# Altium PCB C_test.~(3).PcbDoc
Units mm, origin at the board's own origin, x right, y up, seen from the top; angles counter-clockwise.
Board outline 130.3 x 56.5 mm, 2 copper layers (Top Layer, Bottom Layer), stack 0.137 mm thick; 6 components, 186 nets, 264 pads, 292 vias.
Unrouted connection lines stored in the file: 395.
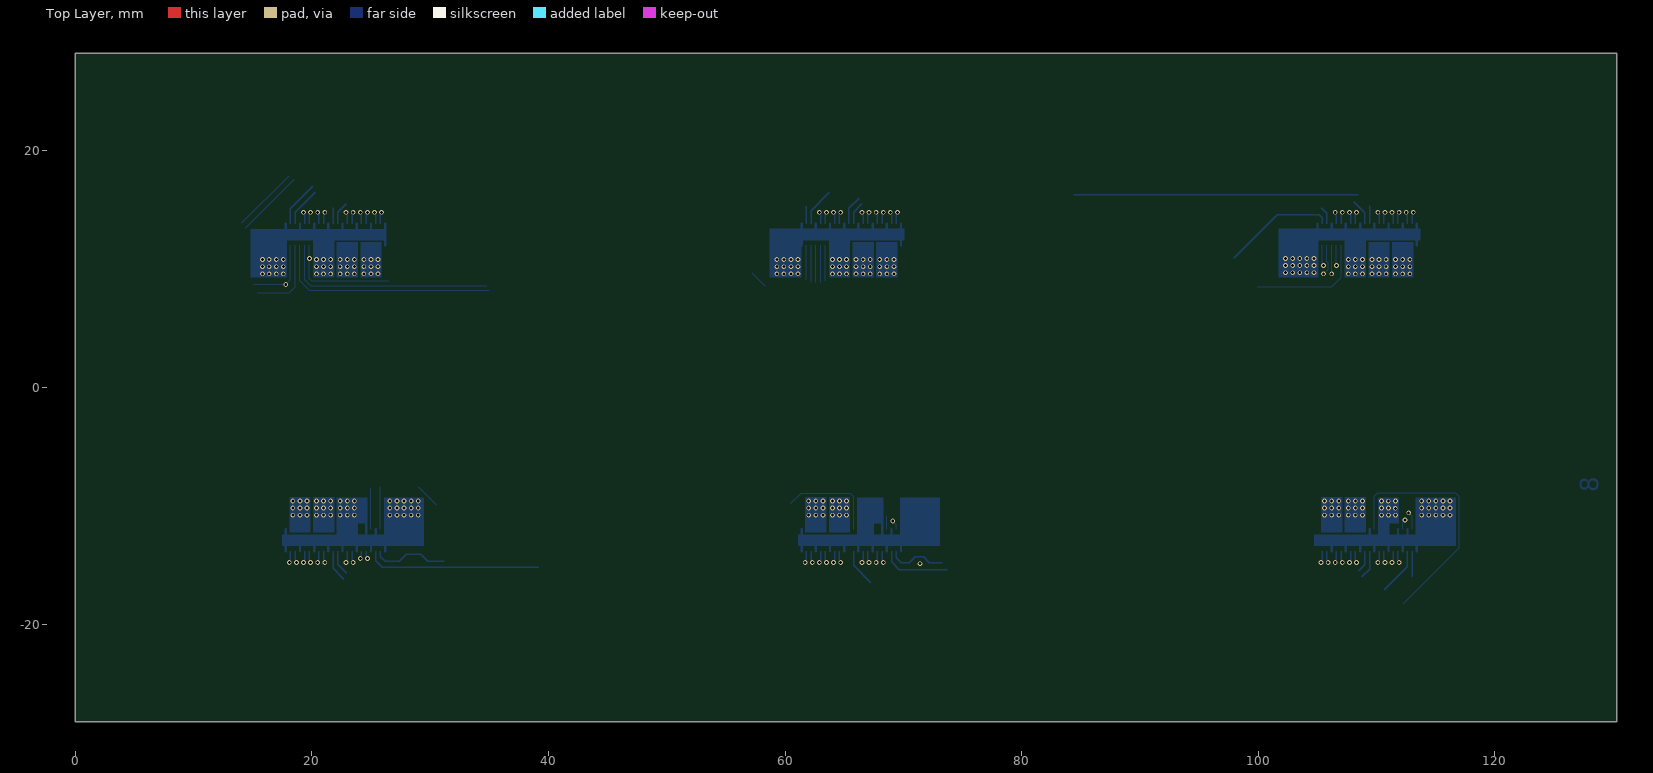
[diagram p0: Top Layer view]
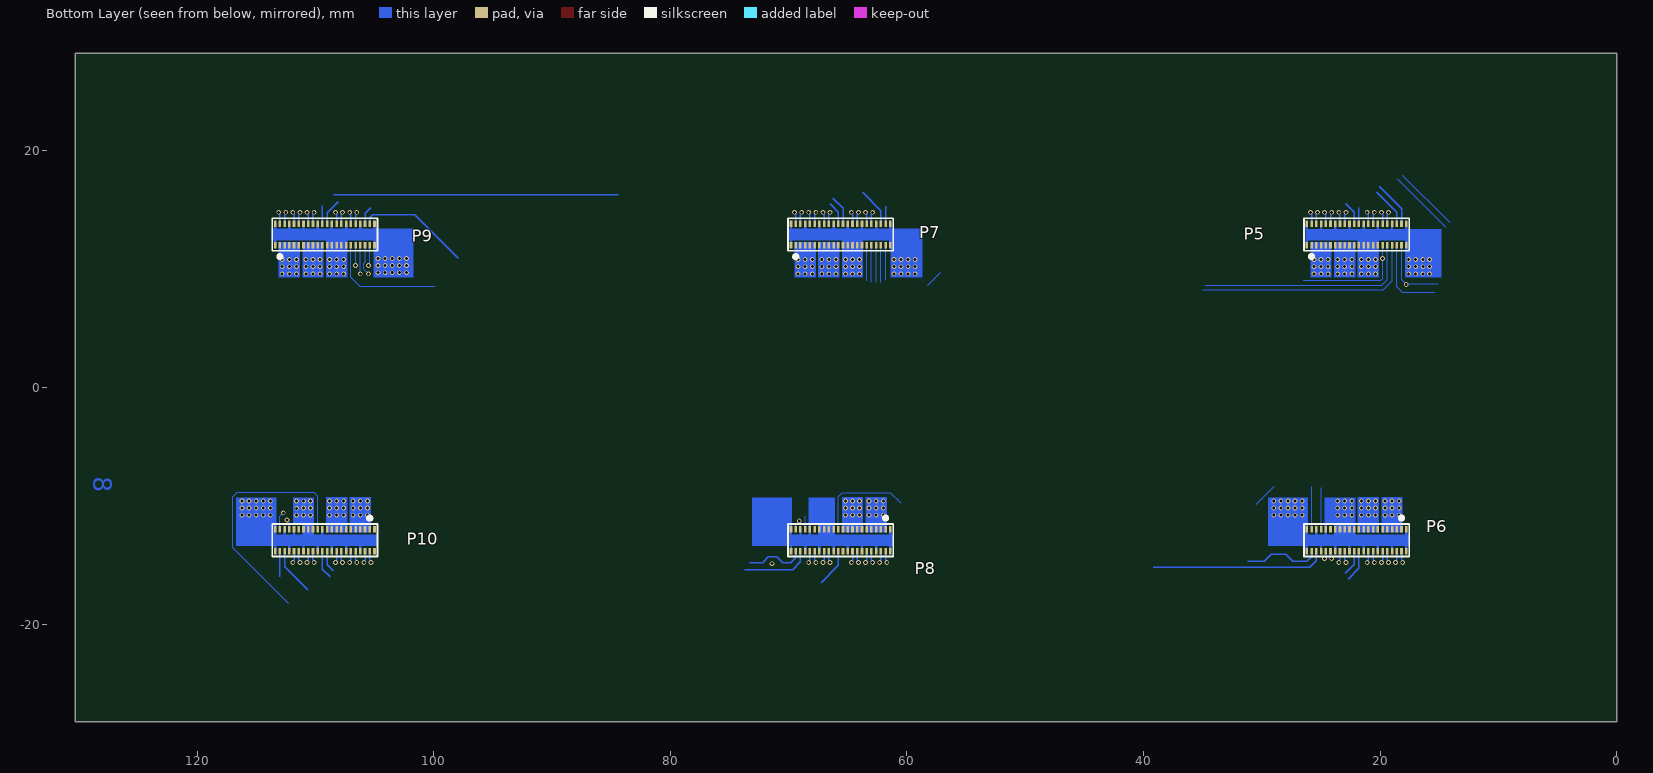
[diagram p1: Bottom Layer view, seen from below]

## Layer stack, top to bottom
Top Solder: solder mask 0.0178, Solder Resist, Dk 4.1
Top Layer: signal copper 0.0175
Dielectric 4: core 0.1016, TU-863, Dk 3.7
Bottom Layer: signal copper 0.0175
Bottom Solder: solder mask 0.0178, Solder Resist, Dk 4.1

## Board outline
0,-28.25 130.3,-28.25 130.3,28.25 0,28.25

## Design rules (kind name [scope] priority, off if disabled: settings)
Clearance [All] p1: gap=0.076 ignorepadtopadclearanceinfootprint=FALSE except(0: Arc-Hole Track-Hole SMDPad-Hole THPad-Hole Via-Hole Fill-Hole Poly-Hole Region-Hole Text-Hole)
Height [All] p1 off: minheight=0 maxheight=25.4 prefheight=12.7
HoleToHoleClearance HoleToHoleClearance_1 [InNet('GND') or InNet('LV_RB') or InNet('1V5A') or InNet('1V5D') or InNet('1V2A') or InNet('1V2B') or InNet('1V2C') or InNet('1V2D') vs InNet('GND') or InNet('LV_RB') or InNet('1V5A') or InNet('1V5D') or InNet('1V2A') or InNet('1V2B') or InNet('1V2C') or InNet('1V2D')] p1: gap=0.15 allowstackedmicrovias=TRUE
HoleToHoleClearance [All] p2: gap=0.254 allowstackedmicrovias=TRUE
MinimumSolderMaskSliver [All] p1: minsoldermaskwidth=0.102
PlaneClearance PlaneClearance_1 [InNetClass('BV')] p1: clearance=0.508
PlaneClearance [All] p2: clearance=0.152
PlaneConnect PlaneConnect_1 [All] p1: planeconnectstyle=Direct reliefexpansion=0.508 reliefentries=4 reliefconductorwidth=0.254 reliefairgap=0.254
PolygonConnect [All] p1: connectstyle=Relief reliefconductorwidth=0.254 reliefentries=4 polygonreliefangle="90 Angle" airgapwidth=0.254
RoomDefinition WP7B [InComponentClass('WP7B')] p1 off: confinementstyle=ConfineIn formatcopy=TRUE lockcomponents=FALSE outline 192.75,16.8 613.75,16.8 613.75,46.8 192.75,46.8
RoomDefinition lpGBT [InComponentClass('lpGBT')] p2 off: confinementstyle=ConfineIn formatcopy=TRUE lockcomponents=FALSE outline 192,-36.75 1047,-36.75 1047,-1.75 192,-1.75
RoutingVias [All] p1: holewidth=0.25 width=0.4 viastyle="Through Hole" minholewidth=0.15 minwidth=0.25 maxholewidth=0.711 maxwidth=1.27
SilkToSilkClearance [All] p1: silktosilkclearance=0.025
SilkToSolderMaskClearance [IsPad] p1: minsilkscreentomaskgap=0.025 clearancetoexposedcopper=TRUE
SolderMaskExpansion SolderMaskExpansion_1 [InPadClass('WP7B40PAD')] p1: expansion=0.038 istentingtop=FALSE
SolderMaskExpansion [All] p2: expansion=0.051 istentingtop=FALSE
Width Width_HS [InNetClass('HS')] p1: maxlimit=0.13 minlimit=0.076 preferedwidth=0.12 bottomlayer_minwidth=0.12 bottomlayer_maxwidth=0.12 minimp=50.000000 maximp=50.000000 favimp=50.000000 // impedance controlled signals
Width [All] p2: maxlimit=2.54 minlimit=0.076 preferedwidth=0.12 toplayer_minwidth=0.076 minimp=50.000000 maximp=50.000000 favimp=50.000000
23 further rules are at their usual default settings.

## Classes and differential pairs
pad class WP7B40PAD: P5-1 P5-2 P5-3 P5-4 P5-5 P5-6 P5-7 P5-8 P5-9 P5-10 P5-11 P5-12 P5-13 P5-14 P5-15 P5-16 P5-17 P5-18 P5-19 P5-20 P5-21 P5-22 P5-23 P5-24 P5-25 P5-26 P5-27 P5-28 P5-29 P5-30 P5-31 P5-32 P5-33 P5-34 P5-35 P5-36 P5-37 P5-38 P5-39 P5-40 P5-41 P5-42 P5-43 P5-44 P6-1 P6-2 P6-3 P6-4 P6-5 P6-6 P6-7 P6-8 P6-9 P6-10 P6-11 P6-12 P6-13 P6-14 P6-15 P6-16 P6-17 P6-18 P6-19 P6-20 P6-21 P6-22 P6-23 P6-24 P6-25 P6-26 P6-27 P6-28 P6-29 P6-30 P6-31 P6-32 P6-33 P6-34 P6-35 P6-36 P6-37 P6-38 P6-39 P6-40 P6-41 P6-42 P6-43 P6-44 P7-1 P7-2 P7-3 P7-4 P7-5 P7-6 P7-7 P7-8 P7-9 P7-10 P7-11 P7-12 P7-13 P7-14 P7-15 P7-16 P7-17 P7-18 P7-19 P7-20 P7-21 P7-22 P7-23 P7-24 P7-25 P7-26 P7-27 P7-28 P7-29 P7-30 P7-31 P7-32 P7-33 P7-34 P7-35 P7-36 P7-37 P7-38 P7-39 P7-40 P7-41 P7-42 P7-43 P7-44 P8-1 P8-2 P8-3 P8-4 P8-5 P8-6 P8-7 P8-8 P8-9 P8-10 P8-11 P8-12 P8-13 P8-14 P8-15 P8-16 P8-17 P8-18 P8-19 P8-20 P8-21 P8-22 P8-23 P8-24 P8-25 P8-26 P8-27 P8-28 P8-29 P8-30 P8-31 P8-32 P8-33 P8-34 P8-35 P8-36 P8-37 P8-38 P8-39 P8-40 P8-41 P8-42 P8-43 P8-44 P9-1 P9-2 P9-3 P9-4 P9-5 P9-6 P9-7 P9-8 P9-9 P9-10 P9-11 P9-12 P9-13 P9-14 P9-15 P9-16 P9-17 P9-18 P9-19 P9-20 P9-21 P9-22 P9-23 P9-24 P9-25 P9-26 P9-27 P9-28 P9-29 P9-30 P9-31 P9-32 P9-33 P9-34 P9-35 P9-36 P9-37 P9-38 P9-39 P9-40 P9-41 P9-42 P9-43 P9-44 P10-1 P10-2 P10-3 P10-4 P10-5 P10-6 P10-7 P10-8 P10-9 P10-10 P10-11 P10-12 P10-13 P10-14 P10-15 P10-16 P10-17 P10-18 P10-19 P10-20 P10-21 P10-22 P10-23 P10-24 P10-25 P10-26 P10-27 P10-28 P10-29 P10-30 P10-31 P10-32 P10-33 P10-34 P10-35 P10-36 P10-37 P10-38 P10-39 P10-40 P10-41 P10-42 P10-43 P10-44

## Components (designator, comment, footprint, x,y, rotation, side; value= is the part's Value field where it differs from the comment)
P5 "WP7B-P040VA1" WP7B-40P 25.8,12 r180 bottom locked
P6 "WP7B-P040VA1" WP7B-40P 18.2,-12 r0 bottom locked
P7 "WP7B-P040VA1" WP7B-40P 69.4,12 r180 bottom locked
P8 "WP7B-P040VA1" WP7B-40P 61.8,-12 r0 bottom locked
P9 "WP7B-P040VA1" WP7B-40P 113,12 r180 bottom locked
P10 "WP7B-P040VA1" WP7B-40P 105.4,-12 r0 bottom locked

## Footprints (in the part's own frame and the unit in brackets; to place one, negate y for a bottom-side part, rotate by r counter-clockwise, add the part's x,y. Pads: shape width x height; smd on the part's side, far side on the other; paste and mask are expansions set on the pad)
WP7B-40P [mm]
  rect 0.22x0.55 smd: 1(0,0) 2(0.4,0) 3(0.8,0) 4(1.2,0) 5(1.6,0) 6(2,0) 7(2.4,0) 8(2.8,0) 9(3.2,0) 10(3.6,0) 11(4,0) 12(4.4,0) 13(4.8,0) 14(5.2,0) 15(5.6,0) 16(6,0) 17(6.4,0) 18(6.8,0) 19(7.2,0) 20(7.6,0) 21(7.6,1.85) 22(7.2,1.85) 23(6.8,1.85) 24(6.4,1.85) 25(6,1.85) 26(5.6,1.85) 27(5.2,1.85) 28(4.8,1.85) 29(4.4,1.85) 30(4,1.85) 31(3.6,1.85) 32(3.2,1.85) 33(2.8,1.85) 34(2.4,1.85) 35(2,1.85) 36(1.6,1.85) 37(1.2,1.85) 38(0.8,1.85) 39(0.4,1.85) 40(0,1.85) 41(-0.4,0) 42(8,0) 43(8,1.85) 44(-0.4,1.85)
  silkscreen extent -0.65,-1 8.25,2.3, body extent -1.5,-0.32 9.1,2.17, height 0.5

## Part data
P5 P6 P7 P8 P9 P10: library part WP7B-40P, "plug"

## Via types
v1: diameter 0.4, hole 0.25, Top Layer to Bottom Layer, 292 vias

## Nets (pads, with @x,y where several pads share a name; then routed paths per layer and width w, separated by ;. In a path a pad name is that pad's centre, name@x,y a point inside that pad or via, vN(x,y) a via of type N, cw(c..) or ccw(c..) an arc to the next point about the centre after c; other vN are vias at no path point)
1V0A: P5.20 P7.20 P9.20 | length 16.6
  Bottom Layer w0.102: 14.4,13.5 18.5,17.6 ; 15.1,8.7 v1(17.8,8.7) 18.2,9.1 P5.20 ; 61.8,9.1 P7.20 ; P9.20 105.4,10.4 v1(105.5,10.3)
1V2_mon0: P5.17 | length 18.5
  Bottom Layer w0.102: P5.17 19.4,9.1 19.9,8.6 34.8,8.6
1V2_mon1: P5.18 | length 19.3
  Bottom Layer w0.102: P5.18 19,9 19.8,8.2 35,8.2
1V2_mon2: P7.17 | length 3.1
  Bottom Layer w0.102: 63,8.9 P7.17
1V2_mon3: P7.18 | length 3.1
  Bottom Layer w0.102: 62.6,8.9 P7.18
1V2_mon4: P9.17 | length 1.7
  Bottom Layer w0.102: v1(106.6,10.3) P9.17
1V2_mon5: P9.18 | length 2.4
  Bottom Layer w0.102: v1(106.2,9.6) P9.18
1V2_RB:  | length 2.1
  Bottom Layer w0.102: 29,-8.4 30.5,-9.9
1V2A: P5.1 P5.2 P5.3 P5.4 P5.5 P5.6 P5.7 P5.8 P5.9 P5.10 P6.6 P6.7 P6.8 P6.9 P6.10
  other v1: 20.4,-10.8 21,-10.8 21.6,-10.8 20.4,-10.2 21,-10.2 21.6,-10.2 20.4,-9.6 21,-9.6 21.6,-9.6 22.4,9.6 23,9.6 23.6,9.6 24.4,9.6 25,9.6 25.6,9.6 22.4,10.2 23,10.2 23.6,10.2 24.4,10.2 25,10.2 25.6,10.2 22.4,10.8 23,10.8 23.6,10.8 24.4,10.8 25,10.8 25.6,10.8
1V2B: P6.1 P6.2 P6.3 P6.4 P6.5 P8.1 P8.2 P8.3 P8.4 P8.5 P8.6 P8.7 P8.8 P8.9 P8.10
  other v1: 18.4,-10.8 19,-10.8 19.6,-10.8 62,-10.8 62.6,-10.8 63.2,-10.8 64,-10.8 64.6,-10.8 65.2,-10.8 18.4,-10.2 19,-10.2 19.6,-10.2 62,-10.2 62.6,-10.2 63.2,-10.2 64,-10.2 64.6,-10.2 65.2,-10.2 18.4,-9.6 19,-9.6 19.6,-9.6 62,-9.6 62.6,-9.6 63.2,-9.6 64,-9.6 64.6,-9.6 65.2,-9.6
1V2C: P7.1 P7.2 P7.3 P7.4 P7.5 P7.6 P7.7 P7.8 P7.9 P7.10 P9.1 P9.2 P9.3 P9.4 P9.5
  other v1: 66,9.6 66.6,9.6 67.2,9.6 68,9.6 68.6,9.6 69.2,9.6 111.6,9.6 112.2,9.6 112.8,9.6 66,10.2 66.6,10.2 67.2,10.2 68,10.2 68.6,10.2 69.2,10.2 111.6,10.2 112.2,10.2 112.8,10.2 66,10.8 66.6,10.8 67.2,10.8 68,10.8 68.6,10.8 69.2,10.8 111.6,10.8 112.2,10.8 112.8,10.8
1V2D: P9.6 P9.7 P9.8 P9.9 P9.10 P10.1 P10.2 P10.3 P10.4 P10.5 P10.6 P10.7 P10.8 P10.9 P10.10
  other v1: 105.6,-10.8 106.2,-10.8 106.8,-10.8 107.6,-10.8 108.2,-10.8 108.8,-10.8 105.6,-10.2 106.2,-10.2 106.8,-10.2 107.6,-10.2 108.2,-10.2 108.8,-10.2 105.6,-9.6 106.2,-9.6 106.8,-9.6 107.6,-9.6 108.2,-9.6 108.8,-9.6 109.6,9.6 110.2,9.6 110.8,9.6 109.6,10.2 110.2,10.2 110.8,10.2 109.6,10.8 110.2,10.8 110.8,10.8
1V5A: 
1V5D: 
2V5F: 
2V5RX: 
2V5TX: 
ADC1: 
ADC2: 
ADC3: 
ADC4: 
ADC6: 
ADC7: 
ADC_IN18: 
ADC_IN21: 
ADC_IN22: 
ADC_IN23: 
ADC_IN24: 
ADC_IN25: 
ADC_IN28: 
ADC_IN29: 
ADC_IN30: 
AGND0: P5.19 | length 12.6
  Bottom Layer w0.102: 14.1,13.9 18.1,17.9 ; 15.4,8 18.1,8 18.6,8.5 P5.19
AGND1: P7.19 | length 4.7
  Bottom Layer w0.102: 57.2,9.7 58.3,8.6 ; 62.2,8.9 P7.19
AGND2: P9.19 | length 2.6
  Bottom Layer w0.102: v1(105.5,9.6) 105.9,10 105.9,10.5 105.8,10.6 P9.19
BV0: 
BV1: 
BV2: 
ECLK0N: P6.27 | length 1
  Bottom Layer w0.12: P6.27 23.4,-14.7 v1(23.5,-14.8)
ECLK0P: P6.28 | length 1
  Bottom Layer w0.12: v1(22.9,-14.8) 23,-14.7 P6.28
ECLK1N: P6.39 | length 1
  Bottom Layer w0.12: P6.39 18.6,-14.7 v1(18.7,-14.8)
ECLK1P: P6.40 | length 1
  Bottom Layer w0.12: v1(18.1,-14.8) 18.2,-14.7 P6.40
ECLK2N: P8.39 | length 1
  Bottom Layer w0.12: P8.39 62.2,-14.7 v1(62.3,-14.8)
ECLK2P: P8.40 | length 1
  Bottom Layer w0.12: v1(61.7,-14.8) 61.8,-14.7 P8.40
ECLK3N: P8.28 | length 1
  Bottom Layer w0.12: v1(66.5,-14.8) 66.6,-14.7 P8.28
ECLK3P: P8.27 | length 1
  Bottom Layer w0.12: P8.27 67,-14.7 v1(67.1,-14.8)
ECLK4N: P10.40 | length 1
  Bottom Layer w0.12: v1(105.3,-14.8) 105.4,-14.7 P10.40
ECLK4P: P10.39 | length 1
  Bottom Layer w0.12: P10.39 105.8,-14.7 v1(105.9,-14.8)
ECLK5N: P10.28 | length 1
  Bottom Layer w0.12: v1(110.1,-14.8) 110.2,-14.7 P10.28
ECLK5P: P10.27 | length 1
  Bottom Layer w0.12: P10.27 110.6,-14.7 v1(110.7,-14.8)
ECLK22N: P9.28 | length 1
  Bottom Layer w0.12: P9.28 108.2,14.7 v1(108.3,14.8)
ECLK22P: P9.27 | length 1
  Bottom Layer w0.12: v1(107.7,14.8) 107.8,14.7 P9.27
ECLK23N: P7.40 | length 1
  Bottom Layer w0.12: P7.40 69.4,14.7 v1(69.5,14.8)
ECLK23P: P7.39 | length 1
  Bottom Layer w0.12: v1(68.9,14.8) 69,14.7 P7.39
ECLK24N: P9.39 | length 1
  Bottom Layer w0.12: v1(112.5,14.8) 112.6,14.7 P9.39
ECLK24P: P9.40 | length 1
  Bottom Layer w0.12: P9.40 113,14.7 v1(113.1,14.8)
ECLK25N: P7.28 | length 1
  Bottom Layer w0.12: P7.28 64.6,14.7 v1(64.7,14.8)
ECLK25P: P7.27 | length 1
  Bottom Layer w0.12: v1(64.1,14.8) 64.2,14.7 P7.27
ECLK26N: P5.40 | length 1
  Bottom Layer w0.12: P5.40 25.8,14.7 v1(25.9,14.8)
ECLK26P: P5.39 | length 1
  Bottom Layer w0.12: v1(25.3,14.8) 25.4,14.7 P5.39
ECLK27N: P5.28 | length 1
  Bottom Layer w0.12: P5.28 21,14.7 v1(21.1,14.8)
ECLK27P: P5.27 | length 1
  Bottom Layer w0.12: v1(20.5,14.8) 20.6,14.7 P5.27
EDIN00N: P6.34 | length 1
  Bottom Layer w0.12: v1(20.5,-14.8) 20.6,-14.7 P6.34
EDIN00P: P6.33 | length 1
  Bottom Layer w0.12: P6.33 21,-14.7 v1(21.1,-14.8)
EDIN02N: P6.25 | length 0.7
  Bottom Layer w0.12: v1(24.1,-14.464) 24.2,-14.464 P6.25
EDIN02P: P6.24 | length 0.7
  Bottom Layer w0.12: P6.24 24.6,-14.464 v1(24.7,-14.464)
EDIN10N: P8.34 | length 1
  Bottom Layer w0.12: v1(64.1,-14.8) 64.2,-14.7 P8.34
EDIN10P: P8.33 | length 1
  Bottom Layer w0.12: P8.33 64.6,-14.7 v1(64.7,-14.8)
EDIN12N: P8.24 | length 1
  Bottom Layer w0.12: P8.24 68.2,-14.7 v1(68.3,-14.8)
EDIN12P: P8.25 | length 1
  Bottom Layer w0.12: v1(67.7,-14.8) 67.8,-14.7 P8.25
EDIN20N: P10.34 | length 1
  Bottom Layer w0.12: v1(107.7,-14.8) 107.8,-14.7 P10.34
EDIN20P: P10.33 | length 1
  Bottom Layer w0.12: P10.33 108.2,-14.7 v1(108.3,-14.8)
EDIN22N: P10.25 | length 1
  Bottom Layer w0.12: v1(111.3,-14.8) 111.4,-14.7 P10.25
EDIN22P: P10.24 | length 1
  Bottom Layer w0.12: P10.24 111.8,-14.7 v1(111.9,-14.8)
EDIN30N: P9.34 | length 1
  Bottom Layer w0.12: P9.34 110.6,14.7 v1(110.7,14.8)
EDIN30P: P9.33 | length 1
  Bottom Layer w0.12: v1(110.1,14.8) 110.2,14.7 P9.33
EDIN32N: P9.25 | length 1
  Bottom Layer w0.12: P9.25 107,14.7 v1(107.1,14.8)
EDIN32P: P9.24 | length 1
  Bottom Layer w0.12: v1(106.5,14.8) 106.6,14.7 P9.24
EDIN40N: P7.34 | length 1
  Bottom Layer w0.12: P7.34 67,14.7 v1(67.1,14.8)
EDIN40P: P7.33 | length 1
  Bottom Layer w0.12: v1(66.5,14.8) 66.6,14.7 P7.33
EDIN42N: P7.25 | length 1
  Bottom Layer w0.12: P7.25 63.4,14.7 v1(63.5,14.8)
EDIN42P: P7.24 | length 1
  Bottom Layer w0.12: v1(62.9,14.8) 63,14.7 P7.24
EDIN50N: P5.34 | length 1
  Bottom Layer w0.12: P5.34 23.4,14.7 v1(23.5,14.8)
EDIN50P: P5.33 | length 1
  Bottom Layer w0.12: v1(22.9,14.8) 23,14.7 P5.33
EDIN52N: P5.25 | length 1
  Bottom Layer w0.12: P5.25 19.8,14.7 v1(19.9,14.8)
EDIN52P: P5.24 | length 1
  Bottom Layer w0.12: v1(19.3,14.8) 19.4,14.7 P5.24
EDOUT00N: P6.36 | length 1
  Bottom Layer w0.12: P6.36 19.8,-14.7 v1(19.9,-14.8)
EDOUT00P: P6.37 | length 1
  Bottom Layer w0.12: v1(19.3,-14.8) 19.4,-14.7 P6.37
EDOUT02N: P8.37 | length 1
  Bottom Layer w0.12: v1(62.9,-14.8) 63,-14.7 P8.37
EDOUT02P: P8.36 | length 1
  Bottom Layer w0.12: P8.36 63.4,-14.7 v1(63.5,-14.8)
EDOUT10N: P10.37 | length 1
  Bottom Layer w0.12: v1(106.5,-14.8) 106.6,-14.7 P10.37
EDOUT10P: P10.36 | length 1
  Bottom Layer w0.12: P10.36 107,-14.7 v1(107.1,-14.8)
EDOUT20N: P9.37 | length 1
  Bottom Layer w0.12: P9.37 111.8,14.7 v1(111.9,14.8)
EDOUT20P: P9.36 | length 1
  Bottom Layer w0.12: v1(111.3,14.8) 111.4,14.7 P9.36
EDOUT22N: P7.37 | length 1
  Bottom Layer w0.12: P7.37 68.2,14.7 v1(68.3,14.8)
EDOUT22P: P7.36 | length 1
  Bottom Layer w0.12: v1(67.7,14.8) 67.8,14.7 P7.36
EDOUT30N: P5.37 | length 1
  Bottom Layer w0.12: P5.37 24.6,14.7 v1(24.7,14.8)
EDOUT30P: P5.36 | length 1
  Bottom Layer w0.12: v1(24.1,14.8) 24.2,14.7 P5.36
GBT_RESET_B: 
GND: P5.11 P5.12 P5.13 P5.14 P5.15 P5.23 P5.26 P5.29 P5.32 P5.35 P5.38 P5.41 P5.42 P5.43 P5.44 P6.11 P6.12 P6.13 P6.14 P6.15 P6.17 P6.19 P6.23 P6.26 P6.29 P6.32 P6.35 P6.38 P6.41 P6.42 P6.43 P6.44 P7.11 P7.12 P7.13 P7.14 P7.15 P7.23 P7.26 P7.29 P7.32 P7.35 P7.38 P7.41 P7.42 P7.43 P7.44 P8.12 P8.13 P8.14 P8.15 P8.17 P8.19 P8.23 P8.26 P8.29 P8.32 P8.35 P8.38 P8.41 P8.42 P8.43 P8.44 P9.11 P9.12 P9.13 P9.14 P9.15 P9.23 P9.26 P9.29 P9.32 P9.35 P9.38 P9.41 P9.42 P9.43 P9.44 P10.11 P10.13 P10.14 P10.15 P10.17 P10.19 P10.23 P10.26 P10.29 P10.32 P10.35 P10.38 P10.41 P10.42 P10.43 P10.44 | length 59
  Bottom Layer w0.2: P6.44 P6.41 ; P5.42 P5.43 ; P6.38 19,-12.9 ; 19,13.1 P5.23 ; P6.35 20.2,-13 ; 20.2,12.9 P5.26 ; P6.32 21.4,-13 ; 21.4,12.9 P5.29 ; P6.29 22.6,-12.9 ; 22.6,13 P5.32 ; P6.26 23.8,-12.9 ; 23.8,13 P5.35 ; 24.6,-12.8 P6.17 24.6,-11.3 ; P6.23 25,-13.1 ; 25,12.9 P5.38 ; 25.4,-12.7 P6.19 ; P6.43 P6.42 ; P5.41 P5.44 ; P8.44 P8.41 ; P7.42 P7.43 ; P8.38 62.6,-12.9 ; 62.6,13.1 P7.23 ; P8.35 63.8,-13 ; 63.8,12.9 P7.26 ; P8.32 65,-13 ; 65,12.9 P7.29 ; P8.29 66.2,-12.9 ; 66.2,13 P7.32 ; P8.26 67.4,-12.9 ; 67.4,13 P7.35 ; 68.2,-12.7 P8.17 68.2,-11.3 ; P8.23 68.6,-13.1 ; 68.6,12.9 P7.38 ; 69,-12.9 P8.19 ; P8.43 P8.42 ; P7.41 P7.44 ; P9.42 P9.43 ; P10.38 106.2,-12.9 ; 106.2,13.1 P9.23 ; P10.35 107.4,-13 ; 107.4,12.9 P9.26 ; P10.32 108.6,-13 ; 108.6,12.9 P9.29 ; 109.4,-12.7 P10.11 ; P10.29 109.8,-12.9 ; 109.8,13 P9.32 ; P10.26 111,-12.9 ; 111,13 P9.35 ; 111.8,-12.8 P10.17 ; P10.23 112.2,-13.1 ; 112.2,12.9 P9.38 ; 112.6,-12.9 P10.19 ; P10.43 P10.42 ; P9.41 P9.44
  other v1: 22.4,-10.8 23,-10.8 23.6,-10.8 26.6,-10.8 27.2,-10.8 27.8,-10.8 28.4,-10.8 29,-10.8 110.4,-10.8 111,-10.8 111.6,-10.8 113.8,-10.8 114.4,-10.8 115,-10.8 115.6,-10.8 116.2,-10.8 111.581,-10.219 22.4,-10.2 23,-10.2 23.6,-10.2 26.6,-10.2 27.2,-10.2 27.8,-10.2 28.4,-10.2 29,-10.2 110.4,-10.2 111,-10.2 113.8,-10.2 114.4,-10.2 115,-10.2 115.6,-10.2 116.2,-10.2 22.4,-9.6 23,-9.6 23.6,-9.6 26.6,-9.6 27.2,-9.6 27.8,-9.6 28.4,-9.6 29,-9.6 110.4,-9.6 110.981,-9.619 111.6,-9.6 113.8,-9.6 114.4,-9.6 115,-9.6 115.6,-9.6 116.2,-9.6 15.827,9.6 16.4,9.6 17,9.6 17.6,9.6 20.4,9.6 21,9.6 21.6,9.6 59.3,9.6 59.9,9.6 60.5,9.6 61.1,9.6 64,9.6 64.6,9.6 65.2,9.6 107.6,9.6 108.2,9.6 108.8,9.6 102.3,9.7 102.9,9.7 103.5,9.7 104.1,9.7 104.7,9.7 15.827,10.2 16.4,10.2 17,10.2 17.6,10.2 20.4,10.2 21,10.2 21.6,10.2 59.3,10.2 59.9,10.2 60.5,10.2 61.1,10.2 64,10.2 64.6,10.2 65.2,10.2 107.6,10.2 108.2,10.2 108.8,10.2 102.3,10.3 102.9,10.3 103.5,10.3 104.1,10.3 104.7,10.3 15.827,10.8 16.4,10.8 17,10.8 17.6,10.8 20.4,10.8 21,10.8 21.6,10.8 59.3,10.8 59.9,10.8 60.5,10.8 61.1,10.8 64,10.8 64.6,10.8 65.2,10.8 107.6,10.8 108.2,10.8 108.8,10.8 102.3,10.9 102.9,10.9 103.5,10.9 104.1,10.9 104.7,10.9
I_1V5: 
I_2V5RX: 
I_2V5TX: 
IC1_SCL: 
IC1_SDA: 
LD_DIS: 
LD_RSTN: 
LV_RB: 
M1SCL: P6.20 P8.20 P10.20 | length 5.9
  Bottom Layer w0.102: P6.20 25.8,-8.4 ; v1(69.1,-11.3) 69.4,-11.6 P8.20 ; v1(112.7,-10.6) 113,-10.9 P10.20
M1SDA: P6.18 P8.18 P10.18 | length 5.5
  Bottom Layer w0.102: P6.18 25,-8.5 ; P8.18 68.6,-10.9 ; P10.18 112.2,-11.4 v1(112.4,-11.2)
  other v1: 71.4,-14.9
M2SCL: 
M2SDA: 
NetC107_1: 
NetC108_1: 
NetC155_1: 
NetC169_1: 
NetD1_1: 
NetD1_2: 
NetIC1_A2: 
NetIC1_G1: 
NetIC1_H1: 
NetIC1_L1: 
NetIC1_M1: 
NetIC1_P2: 
NetIC1_P3: 
NetIC1_R16: 
NetIC1_R17: 
NetIC1_T16: 
NetIC1_T17: 
NetIC1_U16: 
NetIC1_U17: 
NetIC2_19: 
NetIC2_21: 
NetIC5_4: 
NetIC5_5: 
NetIC6_4: 
NetIC7_4: 
NetP4_1: 
NetP8_11: P8.11 P10.12 | length 29.8
  Bottom Layer w0.102: 60.5,-9.8 61.35,-8.95 65.5,-8.95 65.8,-9.25 P8.11 ; P10.12 109.8,-9.2 110.1,-8.9 116.65,-8.9 117,-9.25 117,-13.55 112.25,-18.3
NetP16_1: 
NetP17_1: 
NetQ1_2: 
NetR222_2: 
NetR224_2: 
NetR226_2: 
ON0: 
ON1: 
ON2: 
ON3: 
PG0: 
PG1: 
PG2: 
PG3: 
READY0: 
REFCLKN: 
REFCLKP: 
RSSI: 
RSTB0: P5.16 | length 9.6
  Bottom Layer w0.102: P5.16 v1(19.8,10.9) 19.8,9.2 20,9 26.5,9
RSTB1: P7.16 | length 3
  Bottom Layer w0.102: 63.4,9 P7.16
RSTB2: P9.16 | length 10.1
  Bottom Layer w0.102: 99.9,8.5 106.2,8.5 107,9.3 P9.16
SC_I2C: 
T_EDIN00N: P6.22 | length 14.8
  Bottom Layer w0.12: P6.22 25.4,-14.65 25.95,-15.2 39.2,-15.2
T_EDIN00P: P6.21 | length 6.5
  Bottom Layer w0.12: P6.21 25.8,-14.3 26.2,-14.7 27.4,-14.7 28,-14.1 29.2,-14.1 29.8,-14.7 31.2,-14.7
T_EDIN02N: P6.31 | length 2.7
  Bottom Layer w0.12: P6.31 21.8,-15.3 22.7,-16.2
T_EDIN02P: P6.30 | length 2.2
  Bottom Layer w0.12: P6.30 22.2,-14.95 22.95,-15.7
T_EDIN10N: P8.22 | length 5.9
  Bottom Layer w0.12: P8.22 69,-14.75 69.65,-15.4 73.7,-15.4
T_EDIN10P: P8.21 | length 5
  Bottom Layer w0.12: P8.21 69.4,-14.4 69.8,-14.8 70.5,-14.8 71,-14.3 71.7,-14.3 72.2,-14.8 73.3,-14.8
T_EDIN12N: P8.31
T_EDIN12P: P8.30 | length 3.3
  Bottom Layer w0.12: P8.30 65.8,-15.05 67.25,-16.5
T_EDIN20N: P10.22 | length 4.1
  Bottom Layer w0.12: 110.65,-17.1 112.6,-15.15 P10.22
T_EDIN20P: P10.21 | length 2.2
  Bottom Layer w0.12: 113,-16 P10.21
T_EDIN22N: P10.31 | length 1.9
  Bottom Layer w0.12: 108.5,-15.5 109,-15 P10.31
T_EDIN22P: P10.30 | length 2.4
  Bottom Layer w0.12: 108.75,-16 109.4,-15.35 P10.30
T_EDIN30N: P9.21 | length 9.6
  Bottom Layer w0.12: 97.9,10.9 101.6,14.6 105.15,14.6 105.4,14.35 P9.21
T_EDIN30P: P9.22 | length 1.6
  Bottom Layer w0.12: 105.3,15.2 105.8,14.7 P9.22
T_EDIN32N: P9.30 | length 2.2
  Bottom Layer w0.12: 108.05,15.7 109,14.75 P9.30
T_EDIN32P: P9.31 | length 25.6
  Bottom Layer w0.12: 84.4,16.3 108.45,16.3 ; P9.31 109.4,15.35
T_EDIN40N: P7.22 | length 3.3
  Bottom Layer w0.12: P7.22 62.2,14.95 63.75,16.5
T_EDIN40P: P7.21 | length 1.5
  Bottom Layer w0.12: P7.21 61.8,15.3
T_EDIN42N: P7.31 | length 1.9
  Bottom Layer w0.12: P7.31 65.8,14.8 66.5,15.5
T_EDIN42P: P7.30 | length 2.5
  Bottom Layer w0.12: P7.30 65.4,15.15 66.25,16
T_EDIN50N: P5.22 | length 3.4
  Bottom Layer w0.12: P5.22 18.6,14.8 20.3,16.5
T_EDIN50P: P5.21 | length 3.9
  Bottom Layer w0.12: P5.21 18.2,15.1 20.1,17
T_EDIN52N: P5.31 | length 1.9
  Bottom Layer w0.12: P5.31 22.2,14.8 22.9,15.5
T_EDIN52P: P5.30 | length 1.4
  Bottom Layer w0.12: P5.30 21.8,15.2
Vref: 
pads on no net: P6.16 P8.16 P10.16

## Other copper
Bottom Layer:
  rectangle net GND: 58.7,12.425 70.1,13.425
  rectangle net GND: 14.8,9.3 17.9,12.7
  rectangle net GND: 58.7,9.3 61.4,12.6
  rectangle net GND: 63.7,9.3 65.5,12.6
  rectangle net GND: 107.3,9.3 109.1,12.6
  rectangle net GND: 101.7,9.3 105.1,13.425
  rectangle net GND: 101.7,12.425 113.7,13.425
  rectangle net GND: 20.1,9.3 21.9,12.6
  rectangle net GND: 22.1,-12.6 23.9,-11.4
  rectangle net GND: 22.1,-11.5 24.7,-9.3
  rectangle net GND: 110.1,-12.6 111.1,-11.4
  rectangle net GND: 110.1,-11.5 111.9,-9.3
  rectangle net GND: 113.3,-12.7 116.7,-9.3
  rectangle net GND: 67.4,-11.5 68.3,-9.3
  rectangle net GND: 66.1,-12.6 67.5,-9.3
  rectangle net GND: 69.7,-12.7 73.1,-9.3
  rectangle net GND: 26.1,-12.7 29.5,-9.3
  region net GND: 29.5,-12.425 17.5,-12.425 17.5,-13.425 29.5,-13.425
  region net GND: 73.1,-12.425 61.1,-12.425 61.1,-13.425 73.1,-13.425
  region net GND: 116.7,-12.425 104.7,-12.425 104.7,-13.425 116.7,-13.425
  rectangle net GND: 14.8,12.4 26.3,13.4
  rectangle net 1V2C: 67.7,9.275 69.5,12.275
  rectangle net 1V2C: 65.7,9.275 67.5,12.275
  rectangle net 1V2D: 109.3,9.275 111.1,12.275
  rectangle net 1V2C: 111.3,9.275 113.1,12.275
  region net 1V2D: 109.1,-9.275 107.3,-9.275 107.3,-12.275 109.1,-12.275
  region net 1V2D: 107.1,-9.275 105.3,-9.275 105.3,-12.275 107.1,-12.275
  region net 1V2B: 65.5,-9.275 63.7,-9.275 63.7,-12.275 65.5,-12.275
  region net 1V2B: 63.5,-9.275 61.7,-9.275 61.7,-12.275 63.5,-12.275
  region net 1V2B: 19.9,-9.275 18.1,-9.275 18.1,-12.275 19.9,-12.275
  region net 1V2A: 21.9,-9.275 20.1,-9.275 20.1,-12.275 21.9,-12.275
  rectangle net 1V2A: 22.1,9.275 23.9,12.275
  rectangle net 1V2A: 24.1,9.275 25.9,12.275
  text "8" at 128.746,-8.871 h1.52 r90

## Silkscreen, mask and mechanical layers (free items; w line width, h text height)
Mechanical 1:
  the board outline again, w0.15
Mechanical 14:
  lines w0.15: 5,28.25 38.35,28.25 ; 48.35,28.25 81.95,28.25 ; 125.3,28.25 0,28.25 ; 130.3,-28.2 130.3,23.25 ; 0,28.25 0,-28.25 130.3,-28.25 ; 0,28.25 0,28.25 ; 0,28.25 130.3,28.25 ; 130.3,-28.25 130.3,28.25 ; 130.3,-28.25 130.3,-28.25 ; 130.3,28.25 130.3,28.25

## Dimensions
130.3,-28.25 to 117.8,28.25 on Mechanical 14
0,28.25 to 130.3,7.4 on Mechanical 14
